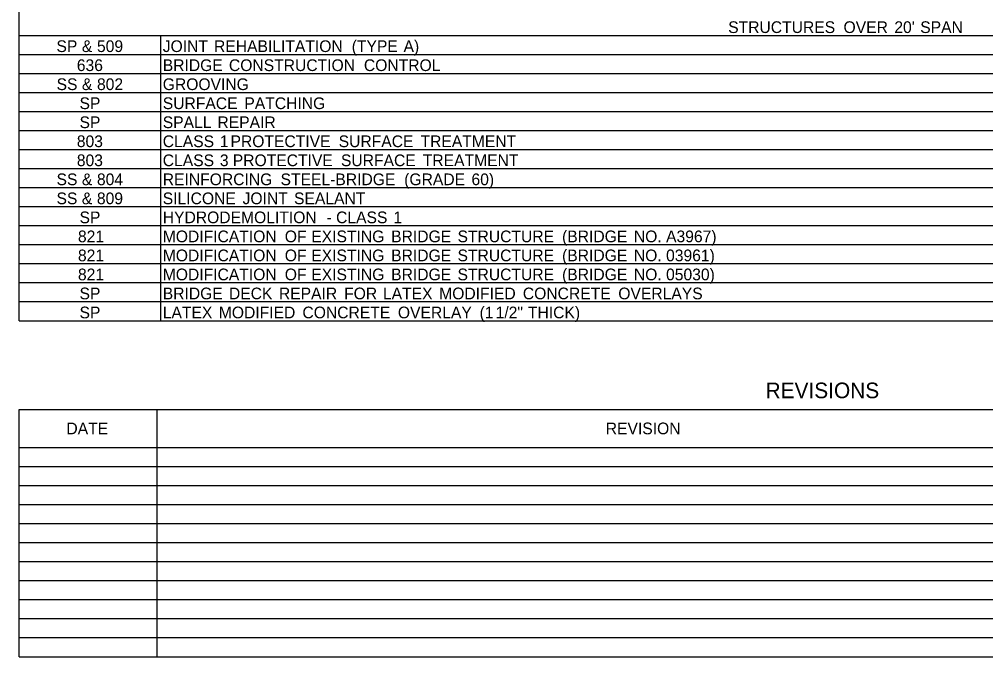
# Model space of a CAD drawing. Extents: x 540541 to 1930787, y -1948574 to 596640.
# Drawn here: x 548275.6 to 548770.9, y -1948488.1 to -1948161.4 of the extents above; entities that cross this region are included whole.
import ezdxf

# ---------------------------------------------------------------- set-up
doc = ezdxf.new("R2010")
doc.units = 0
doc.layers.add('Default', color=7, linetype='Continuous')
doc.layers.add('R_Border', color=7, linetype='Continuous')

msp = doc.modelspace()

# ---------------------------------------------------------------- linework, layer by layer
at = {"layer": 'Default'}
for p, q in [((548275.56, -1948315.82), (548275.56, -1947623.57)), ((548275.56, -1948169.57), (549254.46, -1948169.57)), ((548275.56, -1948169.57), (549254.46, -1948169.57)), ((548348.1, -1948315.82), (548348.1, -1948169.57)), ((548348.1, -1948315.82), (548348.1, -1948169.57)), ((548275.56, -1948179.32), (549254.46, -1948179.32)), ((548275.56, -1948189.07), (549254.46, -1948189.07)), ((548275.56, -1948198.82), (549254.46, -1948198.82)), ((548275.56, -1948208.57), (549254.46, -1948208.57)), ((548275.56, -1948218.32), (549254.46, -1948218.32)), ((548275.56, -1948228.07), (549254.46, -1948228.07)), ((548275.56, -1948237.82), (549254.46, -1948237.82)), ((548275.56, -1948247.57), (549254.46, -1948247.57)), ((548275.56, -1948257.32), (549254.46, -1948257.32)), ((548275.56, -1948267.07), (549254.46, -1948267.07)), ((548275.56, -1948276.82), (549254.46, -1948276.82)), ((548275.56, -1948286.57), (549254.46, -1948286.57)), ((548275.56, -1948296.32), (549254.46, -1948296.32)), ((548275.56, -1948306.07), (549254.46, -1948306.07)), ((548275.56, -1948315.82), (549254.46, -1948315.82)), ((548275.56, -1948361.31), (549228.62, -1948361.31)), ((548275.56, -1948488.06), (548275.56, -1948361.31)), ((548346.25, -1948488.06), (548346.25, -1948361.31)), ((548275.56, -1948380.81), (549228.62, -1948380.81)), ((548275.56, -1948390.56), (549228.62, -1948390.56)), ((548275.56, -1948400.31), (549228.62, -1948400.31)), ((548275.56, -1948410.06), (549228.62, -1948410.06)), ((548275.56, -1948419.81), (549228.62, -1948419.81)), ((548346.25, -1948429.56), (548346.25, -1948419.81)), ((548275.56, -1948429.56), (549228.62, -1948429.56)), ((548346.25, -1948429.56), (548845.45, -1948429.56)), ((548275.56, -1948439.31), (549228.62, -1948439.31)), ((548275.56, -1948449.06), (549228.62, -1948449.06)), ((548275.56, -1948458.81), (549228.62, -1948458.81)), ((548275.56, -1948468.56), (549228.62, -1948468.56)), ((548275.56, -1948478.31), (549228.62, -1948478.31)), ((548275.56, -1948488.06), (549228.62, -1948488.06))]:
    msp.add_line(p, q, dxfattribs=at)
at = {"layer": 'R_Border'}
msp.add_line((548275.56, -1948312.56), (548275.56, -1948312.56), dxfattribs=at)

# ---------------------------------------------------------------- texts
at = {"layer": 'Default'}
for s, height, p in [('STRUCTURES', 6, (548638.91, -1948168.37)), (' OVER', 6, (548695.8, -1948168.37)), (" 20'", 6, (548721.84, -1948168.37)), (' SPAN', 6, (548735.12, -1948168.37)), ('SP', 6, (548294.59, -1948178.12)), (' &', 6, (548305.41, -1948178.12)), (' 509', 6, (548313.14, -1948178.12)), ('JOINT', 6, (548349.08, -1948178.12)), (' REHABILITATION', 6, (548373.13, -1948178.12)), (' (TYPE', 6, (548443.71, -1948178.12)), (' A)', 6, (548470.28, -1948178.12)), ('636', 6, (548305.03, -1948187.87)), ('BRIDGE', 6, (548349.08, -1948187.87)), (' CONSTRUCTION', 6, (548380.77, -1948187.87)), (' CONTROL', 6, (548449.95, -1948187.87)), ('SS', 6, (548294.66, -1948197.62)), (' &', 6, (548305.41, -1948197.62)), (' 802', 6, (548313.14, -1948197.62)), ('GROOVING', 6, (548349.08, -1948197.62)), ('SP', 6, (548306.42, -1948207.37)), ('SURFACE', 6, (548349.08, -1948207.37)), (' PATCHING', 6, (548388.69, -1948207.37)), ('SP', 6, (548306.42, -1948217.12)), ('SPALL', 6, (548349.08, -1948217.12)), (' REPAIR', 6, (548374.88, -1948217.12)), ('803', 6, (548305.03, -1948226.87)), ('CLASS', 6, (548349.08, -1948226.87)), (' 1', 6, (548376.13, -1948226.87)), (' PROTECTIVE', 6, (548381.58, -1948226.87)), (' SURFACE', 6, (548437.03, -1948226.87)), (' TREATMENT', 6, (548478.98, -1948226.87)), ('803', 6, (548305.03, -1948236.62)), ('CLASS', 6, (548349.08, -1948236.62)), (' 3', 6, (548376.13, -1948236.62)), (' PROTECTIVE', 6, (548382.74, -1948236.62)), (' SURFACE', 6, (548438.19, -1948236.62)), (' TREATMENT', 6, (548480.14, -1948236.62)), ('SS', 6, (548294.64, -1948246.37)), (' &', 6, (548305.39, -1948246.37)), (' 804', 6, (548313.12, -1948246.37)), ('REINFORCING', 6, (548349.08, -1948246.37)), (' STEEL-BRIDGE', 6, (548407.24, -1948246.37)), (' (GRADE', 6, (548470.61, -1948246.37)), (' 60)', 6, (548505.1, -1948246.37)), ('SS', 6, (548294.62, -1948256.12)), (' &', 6, (548305.37, -1948256.12)), (' 809', 6, (548313.1, -1948256.12)), ('SILICONE', 6, (548349.08, -1948256.12)), (' JOINT', 6, (548387.76, -1948256.12)), (' SEALANT', 6, (548414.14, -1948256.12)), ('SP', 6, (548306.42, -1948265.87)), ('HYDRODEMOLITION', 6, (548349.08, -1948265.87)), (' CLASS', 6, (548435.69, -1948265.87)), (' 1', 6, (548465.07, -1948265.87)), (' -', 6, (548430.83, -1948265.87)), ('821', 6, (548305.61, -1948275.62)), ('MODIFICATION', 6, (548349.08, -1948275.62)), (' OF', 6, (548409.4, -1948275.62)), (' EXISTING', 6, (548422.99, -1948275.62)), (' BRIDGE', 6, (548463.92, -1948275.62)), (' STRUCTURE', 6, (548497.95, -1948275.62)), (' (BRIDGE', 6, (548551.53, -1948275.62)), (' NO.', 6, (548588.34, -1948275.62)), (' A3967)', 6, (548604.84, -1948275.62)), ('821', 6, (548305.61, -1948285.37)), ('MODIFICATION', 6, (548349.08, -1948285.37)), (' OF', 6, (548409.4, -1948285.37)), (' EXISTING', 6, (548422.99, -1948285.37)), (' BRIDGE', 6, (548463.92, -1948285.37)), (' STRUCTURE', 6, (548497.95, -1948285.37)), (' (BRIDGE', 6, (548551.53, -1948285.37)), (' NO.', 6, (548588.34, -1948285.37)), (' 03961)', 6, (548604.84, -1948285.37)), ('821', 6, (548305.61, -1948295.12)), ('MODIFICATION', 6, (548349.08, -1948295.12)), (' OF', 6, (548409.4, -1948295.12)), (' EXISTING', 6, (548422.99, -1948295.12)), (' BRIDGE', 6, (548463.92, -1948295.12)), (' STRUCTURE', 6, (548497.95, -1948295.12)), (' (BRIDGE', 6, (548551.53, -1948295.12)), (' NO.', 6, (548588.34, -1948295.12)), (' 05030)', 6, (548604.84, -1948295.12)), ('SP', 6, (548306.42, -1948304.87)), ('BRIDGE', 6, (548349.08, -1948304.87)), (' DECK', 6, (548380.77, -1948304.87)), (' REPAIR', 6, (548406.38, -1948304.87)), (' FOR', 6, (548439.81, -1948304.87)), (' LATEX', 6, (548459.72, -1948304.87)), (' MODIFIED', 6, (548488.55, -1948304.87)), (' CONCRETE', 6, (548531.42, -1948304.87)), (' OVERLAYS', 6, (548580.35, -1948304.87)), ('SP', 6, (548306.42, -1948314.62)), ('LATEX', 6, (548349.08, -1948314.62)), (' MODIFIED', 6, (548375.58, -1948314.62)), (' CONCRETE', 6, (548418.45, -1948314.62)), (' OVERLAY', 6, (548467.37, -1948314.62)), (' (1', 6, (548509.25, -1948314.62)), (' 1/2"', 6, (548517.48, -1948314.62)), (' THICK)', 6, (548534.04, -1948314.62)), ('REVISIONS', 8, (548658.06, -1948355.56)), ('DATE', 6, (548299.7, -1948374.06)), ('REVISION', 6, (548576.15, -1948374.06))]:
    msp.add_text(s, height=height, dxfattribs=at).set_placement(p)

doc.saveas('drawing.dxf')
